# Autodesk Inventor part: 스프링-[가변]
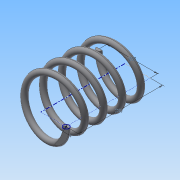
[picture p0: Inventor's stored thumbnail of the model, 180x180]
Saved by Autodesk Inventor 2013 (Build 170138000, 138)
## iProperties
Created: 2015-03
Part Number: 스프링-[가변]
Material: 강철, 탄소
Document SubType Name: Modeling
Designer: Administrator
Density: 7.87 g/cm^3
Mass: 48.2733 g
Surface Area: 62.0009 cm^2
Volume: 6.13384 cm^3
Author: Administrator
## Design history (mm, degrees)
sketch "스케치1"
  geometry: L1 (0, 0)-(17.5, 0); L2 (17.5, 0)-(17.5, 43.5); L3 (17.5, 43.5)-(0, 43.5); L4 (0, 43.5)-(0, 0); C1 r 2 at (17.5, 0)
  constraints: 8 end point, 2 parallel, 1 centre point, 1 coincident, 1 horizontal, 1 perpendicular
  dimensions: "d0" = 4 diameter of C1; "d2" = 35 diameter of L2 L4; "d3" = 43.5 distance of L1.end L2.end (derived)
feature "코일1" sketch "스케치1" pitch "d4" = 10; turns "d6" = 4.5; dims "d5" = 43.5 (= d3), "d7" = 0, angle "d8" = 90 deg, angle "d9" = 90 deg, "d10" = 0, "d11" = 0
node "작업 평면1"
sketch "스케치2"
  geometry: L1 (-19.5, 0)-(-15.5, 0) reference; 1 further point
  constraints: 1 horizontal alignment
extrude "돌출1" cut sketch "스케치2" stored distance "d13" = 10; taper "d14" = 0 deg
node "작업 평면2"
sketch "스케치3"
  geometry: L1 (-19.5, 0)-(-15.5, 0) reference; 1 further point
  constraints: 1 horizontal alignment
extrude "돌출2" cut sketch "스케치3" stored distance "d16" = 10; taper "d17" = 0 deg
node "솔리드1"
node "절단 모서리 투영1"
node "절단 모서리 투영2"
other parameters: "d12" = 0, "d15" = -43.5 (= -d3)
